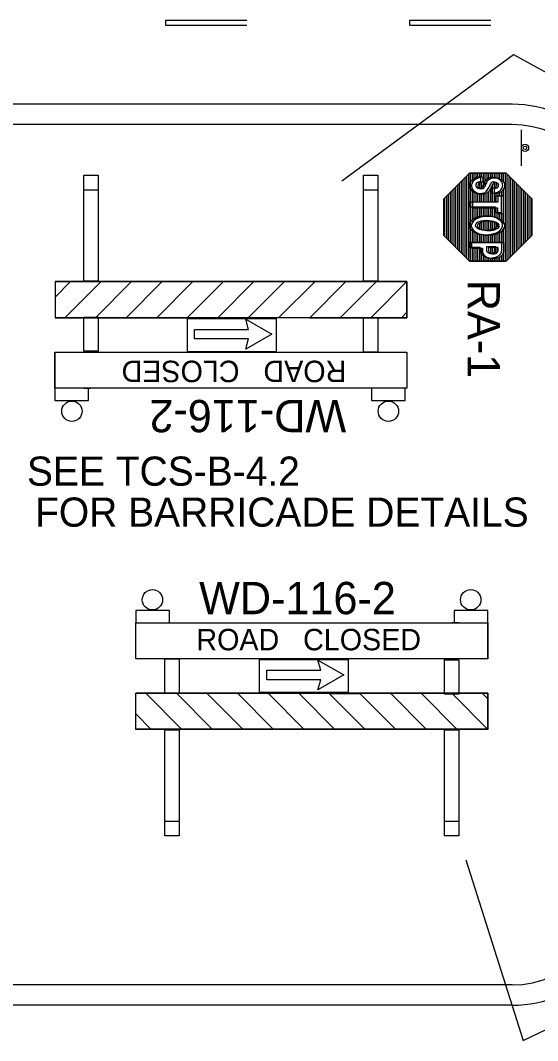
# Model space of a CAD drawing. Extents: x 1806 to 2022, y 110 to 389.
# Drawn here: x 1842.4 to 1873.2, y 223.7 to 284.3 of the extents above; entities that cross this region are included whole.
import ezdxf

# ---------------------------------------------------------------- set-up
doc = ezdxf.new("R2010")
doc.units = 0
for name, color, linetype in [('Level 10', 7, 'Continuous'), ('Level 2', 7, 'Continuous'), ('Level 20', 7, 'Continuous'), ('Level 25', 7, 'Continuous'), ('Level 44', 7, 'Continuous'), ('Level 5', 7, 'Continuous'), ('Level 50', 7, 'Continuous')]:
    doc.layers.add(name, color=color, linetype=linetype)

msp = doc.modelspace()

# ---------------------------------------------------------------- linework, layer by layer
at = {"layer": 'Level 10'}
for p, q in [((1861.54, 274.803), (1871.758, 282.31)), ((1871.758, 282.31), (1878.875, 278.409)), ((1871.667, 279.357), (1839.989, 279.357)), ((1871.667, 278.148), (1839.989, 278.148)), ((1868.91, 234.46), (1872.333, 223.715)), ((1871.667, 227.026), (1839.989, 227.026)), ((1872.333, 223.715), (1878.786, 226.819)), ((1871.667, 225.816), (1839.989, 225.816))]:
    msp.add_line(p, q, dxfattribs=at)
for points in [[(1846.485, 262.491), (1844.481, 262.491), (1844.481, 261.763), (1846.485, 261.763)], [(1865.303, 262.491), (1863.299, 262.491), (1863.299, 261.763), (1865.303, 261.763)], [(1849.288, 248.537), (1851.292, 248.537), (1851.292, 249.265), (1849.288, 249.265)], [(1868.217, 248.537), (1870.221, 248.537), (1870.221, 249.265), (1868.217, 249.265)]]:
    msp.add_lwpolyline(points, close=True, dxfattribs=at)
for centre in [(1845.494, 261.115), (1864.312, 261.115), (1850.279, 249.913), (1869.208, 249.913)]:
    msp.add_circle(centre, 0.606, dxfattribs=at)
for centre, radius, start, end in [((1871.667, 272.1), 7.258, 0, 90), ((1871.667, 272.1), 6.048, 0, 90), ((1871.667, 233.074), 6.048, 270, 359.99999), ((1871.667, 233.074), 7.258, 270, 359.99999)]:
    msp.add_arc(centre, radius, start, end, dxfattribs=at)
at = {"layer": 'Level 2'}
for p, q in [((1855.893, 284.342), (1851.055, 284.342)), ((1851.055, 284.342), (1851.055, 284.052)), ((1870.407, 284.342), (1865.569, 284.342)), ((1865.569, 284.342), (1865.569, 284.052)), ((1851.055, 284.052), (1855.893, 284.052)), ((1865.569, 284.052), (1870.407, 284.052))]:
    msp.add_line(p, q, dxfattribs=at)
at = {"layer": 'Level 20'}
for points in [[(1852.787, 265.978), (1856.003, 265.978), (1855.832, 266.579), (1857.375, 265.696), (1855.832, 264.813), (1856.003, 265.413), (1852.787, 265.413)], [(1857.076, 245.725), (1860.292, 245.725), (1860.121, 246.326), (1861.664, 245.443), (1860.121, 244.56), (1860.292, 245.16), (1857.076, 245.16)]]:
    msp.add_lwpolyline(points, close=True, dxfattribs=at)
at = {"layer": 'Level 44'}
for p, q in [((1872.2, 277.839), (1872.2, 275.705)), ((1869.138, 275.272), (1867.608, 273.743)), ((1871.315, 275.272), (1869.138, 275.272)), ((1872.844, 273.743), (1871.315, 275.272)), ((1869.42, 274.95), (1869.421, 274.952)), ((1869.799, 275.045), (1869.799, 274.745)), ((1869.926, 275.019), (1869.926, 274.719)), ((1870.487, 274.074), (1870.487, 274.402)), ((1870.614, 274.048), (1870.614, 274.374)), ((1867.608, 273.743), (1867.608, 271.565)), ((1869.18, 273.234), (1869.18, 273.566)), ((1869.18, 273.566), (1870.687, 273.566)), ((1870.815, 273.538), (1869.307, 273.538)), ((1869.307, 273.538), (1869.307, 273.207)), ((1870.687, 273.566), (1870.687, 273.918)), ((1870.687, 273.918), (1871.022, 273.918)), ((1871.15, 273.891), (1870.815, 273.891)), ((1870.815, 273.891), (1870.815, 273.538)), ((1871.022, 273.918), (1871.022, 272.898)), ((1871.15, 272.872), (1871.15, 273.891)), ((1872.844, 271.565), (1872.844, 273.743)), ((1870.679, 273.234), (1869.18, 273.234)), ((1869.307, 273.207), (1870.806, 273.207)), ((1870.679, 272.898), (1870.679, 273.234)), ((1871.022, 272.898), (1870.679, 272.898)), ((1870.806, 273.207), (1870.806, 272.872)), ((1870.806, 272.872), (1871.15, 272.872)), ((1870.781, 272.193), (1870.784, 272.18)), ((1871.107, 272.18), (1871.108, 272.17)), ((1867.608, 271.565), (1869.138, 270.036)), ((1869.124, 270.844), (1869.124, 271.162)), ((1869.124, 271.162), (1871.04, 271.162)), ((1871.168, 271.133), (1869.251, 271.133)), ((1869.251, 271.133), (1869.251, 270.816)), ((1871.04, 271.162), (1871.04, 270.626)), ((1871.168, 270.599), (1871.168, 271.133)), ((1871.315, 270.036), (1872.844, 271.565)), ((1869.777, 270.844), (1869.124, 270.844)), ((1869.251, 270.816), (1869.905, 270.816)), ((1869.777, 270.844), (1869.777, 270.644)), ((1869.782, 270.653), (1869.777, 270.844)), ((1869.905, 270.816), (1869.905, 270.616)), ((1870.696, 270.882), (1870.139, 270.882)), ((1870.139, 270.882), (1870.139, 270.678)), ((1870.696, 270.882), (1870.139, 270.882)), ((1870.139, 270.882), (1870.139, 270.678)), ((1870.823, 270.856), (1870.265, 270.856)), ((1870.265, 270.856), (1870.265, 270.651)), ((1870.823, 270.856), (1870.265, 270.856)), ((1870.265, 270.856), (1870.265, 270.651)), ((1870.696, 270.674), (1870.696, 270.882)), ((1870.696, 270.674), (1870.696, 270.882)), ((1870.823, 270.647), (1870.823, 270.856)), ((1870.823, 270.647), (1870.823, 270.856)), ((1869.138, 270.036), (1871.315, 270.036))]:
    msp.add_line(p, q, dxfattribs=at)
msp.add_lwpolyline([(1869.137, 270.036), (1867.608, 271.565), (1867.608, 273.743), (1869.137, 275.272), (1871.315, 275.272), (1872.843, 273.743), (1872.843, 271.565), (1871.315, 270.036)], close=True, dxfattribs=at)
for points in [[(1869.181, 275.272), (1869.181, 270.036)], [(1869.29, 275.272), (1869.29, 274.684)], [(1869.399, 275.272), (1869.399, 274.809)], [(1869.507, 275.272), (1869.507, 274.898)], [(1869.617, 275.272), (1869.617, 274.949)], [(1869.726, 275.272), (1869.726, 274.984)], [(1869.834, 275.272), (1869.834, 275.006)], [(1869.944, 275.272), (1869.944, 274.352)], [(1870.052, 275.272), (1870.052, 274.464)], [(1870.16, 275.272), (1870.16, 274.722)], [(1870.27, 275.272), (1870.27, 274.863)], [(1870.379, 275.272), (1870.379, 274.931)], [(1870.487, 275.272), (1870.487, 274.962)], [(1870.596, 275.272), (1870.596, 274.976)], [(1870.704, 275.272), (1870.704, 274.971)], [(1870.815, 275.272), (1870.815, 274.949)], [(1870.923, 275.272), (1870.923, 274.918)], [(1871.032, 275.272), (1871.032, 274.858)], [(1871.14, 275.272), (1871.14, 274.767)], [(1871.249, 275.272), (1871.249, 270.036)], [(1868.528, 274.661), (1868.528, 270.647)], [(1868.637, 274.77), (1868.637, 270.538)], [(1868.746, 274.88), (1868.746, 270.428)], [(1868.854, 274.989), (1868.854, 270.32)], [(1868.963, 275.097), (1868.963, 270.212)], [(1869.073, 275.206), (1869.073, 270.102)], [(1869.726, 274.676), (1869.726, 274.365)], [(1869.834, 274.709), (1869.834, 274.34)], [(1870.596, 274.692), (1870.596, 273.538)], [(1870.704, 274.709), (1870.704, 274.37)], [(1870.815, 274.661), (1870.815, 274.416)], [(1871.359, 275.228), (1871.359, 270.081)], [(1871.467, 275.118), (1871.467, 270.19)], [(1871.576, 275.01), (1871.576, 270.298)], [(1871.685, 274.901), (1871.685, 270.407)], [(1871.794, 274.792), (1871.794, 270.516)], [(1871.903, 274.684), (1871.903, 270.624)], [(1867.984, 274.118), (1867.984, 271.191)], [(1868.093, 274.226), (1868.093, 271.083)], [(1868.201, 274.334), (1868.201, 270.974)], [(1868.31, 274.444), (1868.31, 270.864)], [(1868.42, 274.553), (1868.42, 270.755)], [(1869.29, 274.348), (1869.29, 272.314)], [(1869.399, 274.204), (1869.399, 273.538)], [(1869.507, 274.126), (1869.507, 273.538)], [(1869.617, 274.073), (1869.617, 273.538)], [(1869.726, 274.038), (1869.726, 273.538)], [(1870.052, 274.048), (1870.052, 273.538)], [(1870.16, 274.078), (1870.16, 273.538)], [(1870.27, 274.161), (1870.27, 273.538)], [(1870.379, 274.308), (1870.379, 273.538)], [(1870.487, 274.553), (1870.487, 273.538)], [(1870.704, 274.053), (1870.704, 273.538)], [(1870.815, 274.078), (1870.815, 273.891)], [(1870.923, 274.109), (1870.923, 273.891)], [(1871.032, 274.169), (1871.032, 273.891)], [(1871.14, 274.265), (1871.14, 273.891)], [(1872.012, 274.575), (1872.012, 270.734)], [(1872.12, 274.464), (1872.12, 270.843)], [(1872.23, 274.356), (1872.23, 270.952)], [(1872.338, 274.247), (1872.338, 271.065)], [(1872.446, 274.139), (1872.446, 271.169)], [(1867.656, 273.791), (1867.656, 271.517)], [(1867.766, 273.894), (1867.766, 271.408)], [(1867.875, 274.008), (1867.875, 271.3)], [(1869.834, 274.031), (1869.834, 273.538)], [(1869.944, 274.031), (1869.944, 273.538)], [(1872.556, 274.031), (1872.556, 271.277)], [(1872.665, 273.922), (1872.665, 271.391)], [(1872.774, 273.812), (1872.774, 271.497)], [(1869.399, 273.207), (1869.399, 272.445)], [(1869.507, 273.207), (1869.507, 272.523)], [(1869.617, 273.207), (1869.617, 272.58)], [(1869.726, 273.207), (1869.726, 272.619)], [(1869.834, 273.207), (1869.834, 272.65)], [(1869.944, 273.207), (1869.944, 272.667)], [(1870.052, 273.207), (1870.052, 272.681)], [(1870.16, 273.207), (1870.16, 272.69)], [(1870.27, 273.207), (1870.27, 272.69)], [(1870.379, 273.203), (1870.379, 272.685)], [(1870.487, 273.207), (1870.487, 272.673)], [(1870.596, 273.207), (1870.596, 272.654)], [(1870.704, 273.207), (1870.704, 272.627)], [(1870.815, 272.872), (1870.815, 272.588)], [(1870.923, 272.872), (1870.923, 272.541)], [(1871.032, 272.872), (1871.032, 272.466)], [(1871.14, 272.872), (1871.14, 272.367)], [(1869.726, 272.301), (1869.726, 271.976)], [(1869.834, 272.35), (1869.834, 271.918)], [(1869.944, 272.384), (1869.944, 271.889)], [(1870.052, 272.405), (1870.052, 271.866)], [(1870.16, 272.418), (1870.16, 271.853)], [(1870.27, 272.418), (1870.27, 271.858)], [(1870.379, 272.411), (1870.379, 271.858)], [(1870.487, 272.405), (1870.487, 271.875)], [(1870.596, 272.375), (1870.596, 271.9)], [(1870.704, 272.345), (1870.704, 271.936)], [(1870.815, 272.292), (1870.815, 271.989)], [(1869.29, 271.971), (1869.29, 271.133)], [(1869.399, 271.84), (1869.399, 271.133)], [(1869.507, 271.762), (1869.507, 271.133)], [(1869.617, 271.706), (1869.617, 271.133)], [(1869.726, 271.662), (1869.726, 271.133)], [(1869.834, 271.63), (1869.834, 271.133)], [(1870.596, 271.617), (1870.596, 271.133)], [(1870.704, 271.644), (1870.704, 271.133)], [(1870.815, 271.684), (1870.815, 271.133)], [(1870.923, 271.731), (1870.923, 271.133)], [(1871.032, 271.8), (1871.032, 271.133)], [(1871.14, 271.906), (1871.14, 271.133)], [(1869.944, 271.608), (1869.944, 271.133)], [(1870.052, 271.59), (1870.052, 271.133)], [(1870.16, 271.583), (1870.16, 271.133)], [(1870.27, 271.578), (1870.27, 271.133)], [(1870.379, 271.587), (1870.379, 271.133)], [(1870.487, 271.596), (1870.487, 271.133)], [(1869.29, 270.816), (1869.29, 270.036)], [(1869.399, 270.816), (1869.399, 270.036)], [(1869.507, 270.816), (1869.507, 270.036)], [(1869.617, 270.816), (1869.617, 270.036)], [(1869.726, 270.816), (1869.726, 270.036)], [(1869.834, 270.816), (1869.834, 270.036)], [(1869.944, 270.5), (1869.944, 270.036)], [(1870.379, 270.856), (1870.379, 270.503)], [(1870.487, 270.861), (1870.487, 270.468)], [(1870.596, 270.856), (1870.596, 270.472)], [(1870.704, 270.856), (1870.704, 270.5)], [(1870.815, 270.856), (1870.815, 270.603)], [(1871.14, 270.5), (1871.14, 270.036)], [(1870.052, 270.35), (1870.052, 270.036)], [(1870.16, 270.276), (1870.16, 270.036)], [(1870.27, 270.238), (1870.27, 270.036)], [(1870.379, 270.208), (1870.379, 270.036)], [(1870.487, 270.194), (1870.487, 270.036)], [(1870.596, 270.197), (1870.596, 270.036)], [(1870.704, 270.212), (1870.704, 270.036)], [(1870.815, 270.238), (1870.815, 270.036)], [(1870.923, 270.29), (1870.923, 270.036)], [(1871.032, 270.359), (1871.032, 270.036)]]:
    msp.add_lwpolyline(points, dxfattribs=at)
for radius in [0.213, 0.107]:
    msp.add_circle((1872.439, 276.768), radius, dxfattribs=at)
for centre, radius, start, end in [((1869.442, 274.545), 0.326, 142.05359, 202.73967), ((1869.759, 274.322), 0.713, 118.41538, 143.65531), ((1869.569, 274.518), 0.326, 142.05359, 202.73966), ((1869.886, 274.296), 0.713, 118.41537, 143.6553), ((1869.843, 274.044), 1.001, 92.38409, 114.95188), ((1869.729, 274.538), 0.223, 140.6966, 181.45727), ((1869.971, 274.017), 1.001, 92.38408, 114.95187), ((1869.708, 274.507), 0.229, 96.87276, 132.74491), ((1869.856, 274.511), 0.223, 140.69659, 181.45726), ((1869.835, 274.48), 0.229, 96.87276, 132.74491), ((1869.794, 274.292), 0.457, 89.01715, 103.51721), ((1869.921, 274.265), 0.457, 89.01714, 103.51721), ((1873.367, 273.198), 3.681, 154.46241, 158.83121), ((1870.465, 274.499), 0.508, 110.4481, 145.11069), ((1873.494, 273.171), 3.68, 154.46241, 158.83121), ((1870.592, 274.472), 0.508, 110.44809, 145.11069), ((1870.487, 274.289), 0.714, 84.81715, 105.91834), ((1871.361, 274.073), 1.12, 147.98164, 160.97904), ((1870.548, 274.582), 0.161, 74.13099, 148.14758), ((1870.614, 274.262), 0.714, 84.81714, 105.91833), ((1870.675, 274.555), 0.161, 74.13098, 148.14757), ((1870.509, 274.189), 0.813, 67.73321, 87.13918), ((1870.574, 274.561), 0.176, 23.8064, 82.24074), ((1870.636, 274.162), 0.813, 67.73321, 87.13917), ((1870.701, 274.534), 0.176, 23.80639, 82.24074), ((1870.579, 274.412), 0.58, 33.3662, 65.67344), ((1870.706, 274.385), 0.58, 33.3662, 65.67344), ((1870.761, 274.545), 0.355, 316.13686, 31.39871), ((1870.888, 274.518), 0.355, 316.13685, 31.39871), ((1869.619, 274.621), 0.521, 203.14132, 234.99056), ((1869.746, 274.594), 0.521, 203.14131, 234.99055), ((1869.834, 274.942), 0.907, 235.50918, 253.2894), ((1869.961, 274.915), 0.907, 235.50917, 253.28939), ((1869.711, 274.554), 0.207, 185.4374, 224.06255), ((1869.709, 274.644), 0.275, 236.25303, 268.73226), ((1869.754, 275.213), 1.154, 261.24702, 273.9864), ((1869.838, 274.527), 0.207, 185.43739, 224.06254), ((1869.836, 274.617), 0.275, 236.25302, 268.73225), ((1869.881, 275.186), 1.154, 261.24702, 273.9864), ((1869.735, 274.58), 0.213, 262.57609, 300.47756), ((1869.862, 274.553), 0.213, 262.57608, 300.47755), ((1869.751, 274.872), 0.815, 275.90969, 291.9865), ((1869.71, 274.587), 0.232, 304.20826, 344.15525), ((1869.878, 274.845), 0.815, 275.90969, 291.98649), ((1869.837, 274.56), 0.232, 304.20825, 344.15524), ((1871.009, 273.13), 1.369, 129.47897, 133.42605), ((1869.576, 274.731), 0.783, 316.24648, 337.92633), ((1871.136, 273.103), 1.368, 129.47897, 133.42605), ((1869.703, 274.704), 0.783, 316.24648, 337.92633), ((1871.488, 274.046), 1.12, 147.98163, 160.97904), ((1870.527, 274.662), 0.27, 260.44122, 309.32441), ((1870.472, 274.905), 0.829, 270.69518, 287.14515), ((1870.654, 274.635), 0.27, 260.44121, 309.3244), ((1870.599, 274.878), 0.829, 270.69517, 287.14514), ((1870.56, 274.575), 0.185, 317.30173, 19.01194), ((1870.567, 274.693), 0.599, 284.56402, 319.00631), ((1870.687, 274.548), 0.184, 317.30172, 19.01193), ((1870.694, 274.666), 0.598, 284.56402, 319.0063), ((1869.891, 270.633), 0.111, 169.79086, 203.54187), ((1870.239, 270.728), 0.471, 196.60197, 209.80906), ((1870.117, 270.633), 0.319, 205.38384, 232.61875), ((1870.018, 270.607), 0.111, 169.79086, 203.54186), ((1870.366, 270.701), 0.471, 196.60197, 209.80905), ((1870.244, 270.606), 0.319, 205.38383, 232.61874), ((1870.351, 270.722), 0.216, 191.91914, 235.7868), ((1870.351, 270.722), 0.216, 191.91914, 235.7868), ((1870.383, 270.775), 0.278, 236.50855, 267.0313), ((1870.383, 270.775), 0.278, 236.50855, 267.0313), ((1870.478, 270.695), 0.216, 191.91913, 235.78679), ((1870.478, 270.695), 0.216, 191.91913, 235.78679), ((1870.51, 270.749), 0.278, 236.50854, 267.03129), ((1870.51, 270.749), 0.278, 236.50854, 267.03129), ((1870.421, 270.805), 0.312, 260.34165, 285.23421), ((1870.421, 270.805), 0.312, 260.34165, 285.23421), ((1870.548, 270.778), 0.312, 260.34164, 285.2342), ((1870.548, 270.778), 0.312, 260.34164, 285.2342), ((1870.459, 270.794), 0.294, 278.60306, 304.21696), ((1870.459, 270.794), 0.294, 278.60306, 304.21696), ((1870.515, 270.706), 0.189, 305.11978, 349.31166), ((1870.515, 270.706), 0.189, 305.11978, 349.31166), ((1870.586, 270.767), 0.294, 278.60306, 304.21695), ((1870.586, 270.767), 0.294, 278.60306, 304.21695), ((1870.642, 270.679), 0.189, 305.11977, 349.31166), ((1870.642, 270.679), 0.189, 305.11977, 349.31166), ((1870.585, 270.754), 0.488, 299.22414, 318.53082), ((1870.585, 270.754), 0.488, 299.22414, 318.53082), ((1870.725, 270.654), 0.318, 314.85284, 355.0441), ((1870.712, 270.727), 0.488, 299.22413, 318.53081), ((1870.712, 270.727), 0.488, 299.22413, 318.53081), ((1870.852, 270.628), 0.318, 314.85284, 355.04409), ((1870.265, 270.767), 0.516, 228.29225, 248.60313), ((1870.265, 270.767), 0.516, 228.29225, 248.60313), ((1870.392, 270.74), 0.516, 228.29224, 248.60312), ((1870.392, 270.74), 0.516, 228.29224, 248.60313), ((1870.467, 271.27), 1.058, 248.31533, 258.66985), ((1870.594, 271.243), 1.058, 248.31532, 258.66984), ((1870.404, 271.029), 0.81, 259.75207, 272.79164), ((1870.404, 271.029), 0.81, 259.75207, 272.79164), ((1870.531, 271.002), 0.81, 259.75206, 272.79163), ((1870.531, 271.002), 0.81, 259.75206, 272.79163), ((1870.384, 271.226), 1.008, 273.39027, 285.65974), ((1870.512, 271.199), 1.008, 273.39026, 285.65974), ((1870.538, 270.76), 0.519, 283.06738, 303.76202), ((1870.665, 270.734), 0.519, 283.06737, 303.76201)]:
    msp.add_arc(centre, radius, start, end, dxfattribs=at)
for centre, major_axis, ratio, start_param, end_param in [((1870.11, 272.162), (-0.998, 0.007), 0.558644, 4.129576, 6.939747), ((1870.237, 272.136), (-0.998, 0.007), 0.558644, 3.185857, 9.451311), ((1870.133, 272.162), (-0.652, -0.003), 0.432619, 3.890436, 7.165085), ((1870.26, 272.136), (-0.652, -0.003), 0.432619, 3.239639, 9.473919), ((1870.133, 272.162), (-0.652, -0.003), 0.432619, 3.239639, 3.888884), ((1870.11, 272.162), (-0.998, 0.007), 0.558644, 3.185857, 4.129398), ((1870.11, 272.162), (-0.998, 0.007), 0.558644, 0.656861, 3.168126), ((1870.133, 272.162), (-0.652, -0.003), 0.432619, 0.881967, 3.190734)]:
    msp.add_ellipse(centre, major_axis=major_axis, ratio=ratio, start_param=start_param, end_param=end_param, dxfattribs=at)
at = {"layer": 'Level 5'}
for p, q in [((1846.196, 274.283), (1847.054, 274.283)), ((1862.833, 274.283), (1863.691, 274.283)), ((1865.415, 268.815), (1844.49, 268.815)), ((1844.49, 268.815), (1844.49, 266.672)), ((1865.415, 268.815), (1844.49, 268.815)), ((1844.49, 268.815), (1844.49, 266.672)), ((1865.415, 268.815), (1865.415, 266.672)), ((1865.415, 268.815), (1865.415, 266.672)), ((1865.415, 266.672), (1844.49, 266.672)), ((1865.415, 266.672), (1844.49, 266.672)), ((1863.7, 266.672), (1863.271, 266.672)), ((1844.481, 264.635), (1844.481, 262.491)), ((1844.481, 264.635), (1844.481, 262.491)), ((1844.481, 264.635), (1865.406, 264.635)), ((1844.481, 262.491), (1844.481, 264.635)), ((1847.054, 264.678), (1847.054, 264.635)), ((1863.691, 264.678), (1863.691, 264.635)), ((1865.406, 264.635), (1865.406, 262.491)), ((1865.406, 262.491), (1844.481, 262.491)), ((1846.196, 262.491), (1846.625, 262.491)), ((1849.296, 246.393), (1849.296, 248.537)), ((1849.296, 248.537), (1870.221, 248.537)), ((1868.506, 248.537), (1868.077, 248.537)), ((1870.221, 246.393), (1870.221, 248.537)), ((1870.221, 246.393), (1870.221, 248.537)), ((1870.221, 248.537), (1870.221, 246.393)), ((1870.221, 246.393), (1849.296, 246.393)), ((1851.011, 246.35), (1851.011, 246.393)), ((1867.648, 246.35), (1867.648, 246.393)), ((1870.221, 244.356), (1849.296, 244.356)), ((1849.296, 242.213), (1849.296, 244.356)), ((1870.221, 244.356), (1849.296, 244.356)), ((1849.296, 242.213), (1849.296, 244.356)), ((1868.506, 244.356), (1868.077, 244.356)), ((1870.221, 242.213), (1870.221, 244.356)), ((1870.221, 242.213), (1870.221, 244.356)), ((1870.221, 242.213), (1849.296, 242.213)), ((1870.221, 242.213), (1849.296, 242.213)), ((1851.869, 236.745), (1851.011, 236.745)), ((1868.506, 236.745), (1867.648, 236.745))]:
    msp.add_line(p, q, dxfattribs=at)
for points in [[(1847.054, 268.837), (1846.196, 268.837), (1846.196, 275.141), (1847.054, 275.141)], [(1863.691, 268.837), (1862.833, 268.837), (1862.833, 275.141), (1863.691, 275.141)], [(1844.49, 267.902), (1844.49, 266.672), (1845.079, 266.672), (1847.223, 268.816), (1845.404, 268.816)], [(1846.899, 266.672), (1848.718, 266.672), (1850.861, 268.816), (1849.042, 268.816)], [(1850.537, 266.672), (1852.356, 266.672), (1854.5, 268.816), (1852.681, 268.816)], [(1854.175, 266.672), (1855.985, 266.685), (1858.13, 268.829), (1856.319, 268.816)], [(1857.805, 266.685), (1859.633, 266.672), (1861.777, 268.816), (1859.949, 268.829)], [(1861.452, 266.672), (1863.272, 266.672), (1865.416, 268.816), (1863.596, 268.816)], [(1865.416, 266.672), (1865.416, 266.996), (1865.091, 266.672)], [(1847.054, 264.678), (1846.196, 264.678), (1846.196, 266.716), (1847.054, 266.716)], [(1847.054, 264.678), (1846.196, 264.678), (1846.196, 266.672), (1847.054, 266.672)], [(1852.363, 266.622), (1857.637, 266.622), (1857.637, 264.649), (1852.363, 264.649)], [(1863.691, 264.635), (1862.833, 264.635), (1862.833, 266.672), (1863.691, 266.672)], [(1865.406, 262.491), (1844.481, 262.491), (1844.481, 264.635), (1865.406, 264.635)], [(1849.296, 248.537), (1870.221, 248.537), (1870.221, 246.393), (1849.296, 246.393)], [(1851.011, 246.393), (1851.869, 246.393), (1851.869, 244.356), (1851.011, 244.356)], [(1856.652, 246.369), (1861.926, 246.369), (1861.926, 244.396), (1856.652, 244.396)], [(1867.648, 246.35), (1868.506, 246.35), (1868.506, 244.356), (1867.648, 244.356)], [(1867.648, 246.35), (1868.506, 246.35), (1868.506, 244.312), (1867.648, 244.312)], [(1849.296, 243.126), (1849.296, 244.356), (1849.885, 244.356), (1852.029, 242.212), (1850.21, 242.212)], [(1851.705, 244.356), (1853.524, 244.356), (1855.667, 242.212), (1853.848, 242.212)], [(1855.343, 244.356), (1857.162, 244.356), (1859.306, 242.212), (1857.487, 242.212)], [(1858.981, 244.356), (1860.791, 244.343), (1862.936, 242.199), (1861.125, 242.212)], [(1862.611, 244.343), (1864.439, 244.356), (1866.583, 242.212), (1864.755, 242.199)], [(1866.258, 244.356), (1868.078, 244.356), (1870.222, 242.212), (1868.402, 242.212)], [(1870.222, 244.356), (1870.222, 244.032), (1869.897, 244.356)], [(1851.011, 242.191), (1851.869, 242.191), (1851.869, 235.887), (1851.011, 235.887)], [(1867.648, 242.191), (1868.506, 242.191), (1868.506, 235.887), (1867.648, 235.887)]]:
    msp.add_lwpolyline(points, close=True, dxfattribs=at)
for points in [[(1844.49, 267.902), (1845.404, 268.816), (1844.49, 268.816), (1844.49, 267.902)], [(1845.079, 266.672), (1846.899, 266.672), (1849.042, 268.816), (1847.223, 268.816), (1845.079, 266.672)], [(1848.718, 266.672), (1850.537, 266.672), (1852.681, 268.816), (1850.861, 268.816), (1848.718, 266.672)], [(1854.5, 268.816), (1852.356, 266.672), (1854.175, 266.672), (1856.319, 268.816), (1854.5, 268.816)], [(1858.13, 268.829), (1855.985, 266.685), (1857.805, 266.685), (1859.949, 268.829), (1858.13, 268.829)], [(1861.777, 268.816), (1859.633, 266.672), (1861.452, 266.672), (1863.596, 268.816), (1861.777, 268.816)], [(1865.416, 268.816), (1863.272, 266.672), (1865.091, 266.672), (1865.416, 266.996), (1865.416, 268.816)], [(1849.885, 244.356), (1851.705, 244.356), (1853.848, 242.212), (1852.029, 242.212), (1849.885, 244.356)], [(1853.524, 244.356), (1855.343, 244.356), (1857.487, 242.212), (1855.667, 242.212), (1853.524, 244.356)], [(1859.306, 242.212), (1857.162, 244.356), (1858.981, 244.356), (1861.125, 242.212), (1859.306, 242.212)], [(1862.936, 242.199), (1860.791, 244.343), (1862.611, 244.343), (1864.755, 242.199), (1862.936, 242.199)], [(1866.583, 242.212), (1864.439, 244.356), (1866.258, 244.356), (1868.402, 242.212), (1866.583, 242.212)], [(1870.222, 242.212), (1868.078, 244.356), (1869.897, 244.356), (1870.222, 244.032), (1870.222, 242.212)], [(1849.296, 243.126), (1850.21, 242.212), (1849.296, 242.212), (1849.296, 243.126)]]:
    msp.add_lwpolyline(points, dxfattribs=at)

# ---------------------------------------------------------------- texts
at = {"layer": 'Level 25'}
msp.add_text('ROAD   CLOSED', height=1.27499, rotation=180, dxfattribs=at).set_placement((1861.808, 264.12))
msp.add_text('ROAD   CLOSED', height=1.27499, dxfattribs=at).set_placement((1852.894, 246.908))
at = {"layer": 'Level 50'}
for s, height, rotation, p in [('RA-1', 1.92, 269.99999, (1869.021, 268.927)), ('WD-116-2', 1.92, 180, (1861.803, 261.788)), ('SEE TCS-B-4.2', 1.733, 360, (1842.82, 256.69)), ('FOR BARRICADE DETAILS', 1.73275, 360, (1843.301, 254.256)), ('WD-116-2', 1.92, 360, (1853.057, 249.054))]:
    msp.add_text(s, height=height, rotation=rotation, dxfattribs=at).set_placement(p)

doc.saveas('drawing.dxf')
